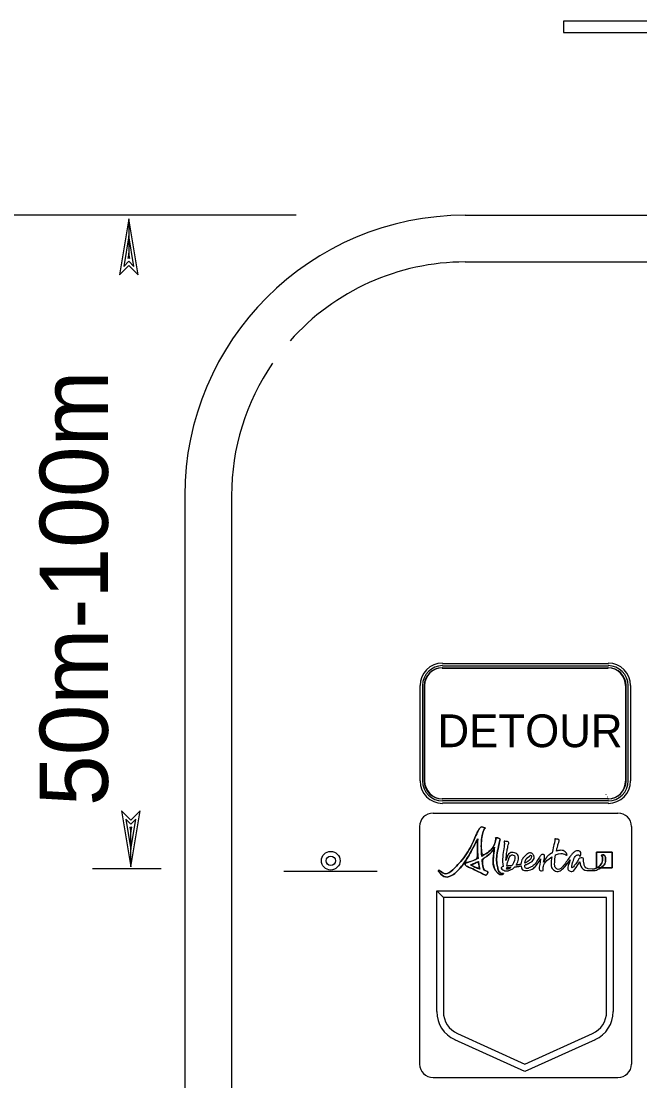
# Model space of a CAD drawing. Extents: x 1806 to 2022, y 110 to 389.
# Drawn here: x 1884.37 to 1900.38, y 193.73 to 221.16 of the extents above; entities that cross this region are included whole.
import ezdxf

# ---------------------------------------------------------------- set-up
doc = ezdxf.new("R2010")
doc.units = 0
for name, color, linetype in [('Level 1', 7, 'Continuous'), ('Level 10', 7, 'Continuous'), ('Level 2', 7, 'Continuous'), ('Level 44', 7, 'Continuous'), ('Level 53', 7, 'Continuous')]:
    doc.layers.add(name, color=color, linetype=linetype)

msp = doc.modelspace()

# ---------------------------------------------------------------- linework, layer by layer
at = {"layer": 'Level 1'}
for points in [[(1887.157, 216.049), (1886.915, 214.597), (1887.157, 214.839), (1887.399, 214.597), (1887.157, 216.049), (1887.157, 215.604), (1887.026, 214.815), (1887.157, 214.946), (1887.288, 214.815), (1887.157, 215.604), (1887.157, 215.154), (1887.133, 215.018), (1887.157, 215.043), (1887.181, 215.018), (1887.157, 215.154), (1887.157, 215.043)], [(1887.207, 199.269), (1887.449, 200.721), (1887.207, 200.479), (1886.965, 200.721), (1887.207, 199.269), (1887.207, 199.714), (1887.338, 200.503), (1887.207, 200.372), (1887.076, 200.503), (1887.207, 199.714), (1887.207, 200.164), (1887.231, 200.3), (1887.207, 200.275), (1887.183, 200.3), (1887.207, 200.164), (1887.207, 200.275)]]:
    msp.add_lwpolyline(points, dxfattribs=at)
at = {"layer": 'Level 10'}
for p, q in [((1891.489, 216.139), (1875.288, 216.139)), ((1895.86, 216.139), (1957.331, 216.139)), ((1895.86, 214.93), (1957.331, 214.93)), ((1888.603, 208.881), (1888.603, 146.057)), ((1889.812, 208.881), (1889.812, 146.057)), ((1887.99, 199.217), (1886.212, 199.217))]:
    msp.add_line(p, q, dxfattribs=at)
for radius, start, end in [(7.258, 90, 180), (6.048, 90, 138.5343), (6.048, 145.494, 180)]:
    msp.add_arc((1895.86, 208.881), radius, start, end, dxfattribs=at)
at = {"layer": 'Level 2'}
for p, q in [((1903.243, 221.163), (1898.405, 221.163)), ((1898.405, 221.163), (1898.405, 220.873)), ((1898.405, 220.873), (1903.243, 220.873)), ((1895.027, 200.661), (1899.812, 200.661)), ((1895.027, 200.661), (1899.812, 200.661)), ((1894.68, 200.314), (1894.68, 194.16)), ((1900.159, 200.314), (1900.159, 194.16)), ((1895.122, 195.522), (1895.122, 198.649)), ((1895.122, 198.649), (1895.293, 198.478)), ((1895.293, 198.478), (1895.122, 198.649)), ((1895.122, 198.649), (1899.688, 198.649)), ((1899.688, 198.649), (1899.688, 195.522)), ((1895.293, 198.478), (1895.293, 195.522)), ((1899.517, 198.478), (1895.293, 198.478)), ((1899.517, 195.522), (1899.517, 198.478)), ((1897.405, 193.969), (1895.59, 194.794)), ((1895.661, 194.95), (1897.405, 194.157)), ((1897.405, 194.157), (1899.149, 194.95)), ((1899.22, 194.794), (1897.405, 193.969)), ((1895.027, 193.813), (1899.812, 193.813))]:
    msp.add_line(p, q, dxfattribs=at)
for centre, radius, start, end in [((1895.027, 200.314), 0.347, 90, 180), ((1899.812, 200.314), 0.347, 0, 90), ((1895.921, 195.522), 0.799, 180, 245.5432), ((1895.921, 195.522), 0.628, 180, 245.5432), ((1898.889, 195.522), 0.628, 294.4568, 0), ((1898.889, 195.522), 0.799, 294.4568, 0), ((1895.027, 194.16), 0.347, 180, 270), ((1899.812, 194.16), 0.347, 270, 0)]:
    msp.add_arc(centre, radius, start, end, dxfattribs=at)
at = {"layer": 'Level 44'}
for p, q in [((1895.261, 204.415), (1899.552, 204.415)), ((1895.271, 204.536), (1899.562, 204.536)), ((1895.271, 204.471), (1899.562, 204.471)), ((1895.271, 204.417), (1899.562, 204.417)), ((1895.271, 204.417), (1899.562, 204.417)), ((1895.271, 204.417), (1899.562, 204.417)), ((1894.696, 201.496), (1894.696, 203.961)), ((1894.761, 201.496), (1894.761, 203.961)), ((1894.805, 201.494), (1894.805, 203.959)), ((1894.815, 201.496), (1894.815, 203.961)), ((1894.815, 201.496), (1894.815, 203.961)), ((1894.815, 201.496), (1894.815, 203.961)), ((1900.004, 203.959), (1900.004, 201.494)), ((1900.014, 203.961), (1900.014, 201.496)), ((1900.014, 203.961), (1900.014, 201.496)), ((1900.014, 203.961), (1900.014, 201.496)), ((1900.068, 203.961), (1900.068, 201.496)), ((1900.133, 203.961), (1900.133, 201.496)), ((1899.505, 201.137), (1899.509, 201.139)), ((1899.552, 201.031), (1895.261, 201.031)), ((1899.562, 201.033), (1895.271, 201.033)), ((1899.562, 201.033), (1895.271, 201.033)), ((1899.562, 201.033), (1895.271, 201.033)), ((1899.562, 200.979), (1895.271, 200.979)), ((1899.562, 200.914), (1895.271, 200.914)), ((1897.627, 201.025), (1897.627, 201.025)), ((1897.637, 201.027), (1897.637, 201.027)), ((1897.637, 201.027), (1897.637, 201.027)), ((1897.637, 201.027), (1897.637, 201.027)), ((1899.534, 201.079), (1899.538, 201.081)), ((1899.558, 201.031), (1899.562, 201.033)), ((1891.165, 199.157), (1893.584, 199.157))]:
    msp.add_line(p, q, dxfattribs=at)
for radius in [0.242, 0.121]:
    msp.add_circle((1892.379, 199.428), radius, dxfattribs=at)
for centre, radius, start, end in [((1895.271, 203.962), 0.581, 90, 180), ((1895.271, 203.962), 0.516, 90, 180), ((1895.261, 203.96), 0.462, 90, 180), ((1895.271, 203.962), 0.462, 90, 180), ((1895.271, 203.962), 0.462, 90, 180), ((1895.271, 203.962), 0.462, 90, 180), ((1899.548, 203.96), 0.462, 0, 90), ((1899.558, 203.962), 0.581, 0, 90), ((1899.558, 203.962), 0.516, 0, 90), ((1899.558, 203.962), 0.462, 0, 90), ((1899.558, 203.962), 0.462, 0, 90), ((1899.558, 203.962), 0.462, 0, 90), ((1895.271, 201.492), 0.581, 180, 270), ((1895.271, 201.492), 0.516, 180, 270), ((1895.261, 201.49), 0.462, 180, 270), ((1895.271, 201.492), 0.462, 180, 270), ((1895.271, 201.492), 0.462, 180, 270), ((1895.271, 201.492), 0.462, 180, 270), ((1899.548, 201.49), 0.462, 270, 0), ((1899.558, 201.492), 0.462, 270, 0), ((1899.558, 201.492), 0.462, 270, 0), ((1899.558, 201.492), 0.581, 270, 0), ((1899.558, 201.492), 0.516, 270, 0), ((1899.558, 201.492), 0.462, 270, 0)]:
    msp.add_arc(centre, radius, start, end, dxfattribs=at)
at = {"layer": 'Level 53'}
msp.add_line((1899.368, 199.244), (1899.267, 199.244), dxfattribs=at)
msp.add_lwpolyline([(1899.368, 199.244), (1899.663, 199.244), (1899.663, 199.652), (1899.256, 199.652), (1899.256, 199.244), (1899.267, 199.244)], dxfattribs=at)
for points, degree in [([(1896.814, 199.096), (1896.77, 199.103), (1896.713, 199.163), (1896.695, 199.261), (1896.664, 199.437), (1896.682, 199.611), (1896.734, 199.871), (1896.744, 199.92), (1896.778, 200.005), (1896.671, 200.021), (1896.637, 200.027), (1896.655, 200.01), (1896.645, 199.965), (1896.604, 199.772), (1896.446, 199.632), (1896.287, 199.539), (1896.271, 199.76), (1896.278, 200.006), (1896.319, 200.157), (1896.354, 200.284), (1896.396, 200.261), (1896.344, 200.287), (1896.29, 200.315), (1896.231, 200.278), (1896.184, 200.184), (1896.136, 200.089), (1895.918, 199.575), (1895.569, 199.227), (1895.39, 199.05), (1895.229, 199.141), (1895.196, 199.169), (1895.17, 199.191), (1895.16, 199.157), (1895.193, 199.121), (1895.337, 198.966), (1895.548, 199.055), (1895.625, 199.132), (1895.837, 199.344), (1896.084, 199.801), (1896.184, 199.995), (1896.175, 199.886), (1896.172, 199.703), (1896.192, 199.488), (1896.084, 199.435), (1895.987, 199.404), (1895.942, 199.392), (1895.892, 199.379), (1895.862, 199.359), (1895.861, 199.336), (1895.86, 199.311), (1895.893, 199.29), (1895.941, 199.267), (1896.026, 199.227), (1896.277, 199.108), (1896.339, 199.072), (1896.392, 199.042), (1896.417, 199.066), (1896.433, 199.099), (1896.454, 199.142), (1896.397, 199.167), (1896.343, 199.183), (1896.322, 199.256), (1896.305, 199.354), (1896.294, 199.461), (1896.422, 199.54), (1896.547, 199.644), (1896.619, 199.775), (1896.601, 199.665), (1896.555, 199.295), (1896.672, 199.138), (1896.697, 199.103), (1896.754, 199.066), (1896.81, 199.071), (1896.836, 199.074), (1896.849, 199.091), (1896.847, 199.096), (1896.844, 199.102), (1896.829, 199.094), (1896.814, 199.096)], 3), ([(1896.287, 199.539), (1896.271, 199.76), (1896.278, 200.006), (1896.319, 200.157), (1896.354, 200.284), (1896.396, 200.261), (1896.344, 200.287), (1896.29, 200.315), (1896.231, 200.278), (1896.184, 200.184), (1896.136, 200.089), (1895.918, 199.575), (1895.569, 199.227), (1895.39, 199.05), (1895.229, 199.141), (1895.196, 199.169), (1895.17, 199.191), (1895.16, 199.157), (1895.193, 199.121), (1895.337, 198.966), (1895.548, 199.055), (1895.625, 199.132), (1895.837, 199.344), (1896.084, 199.801), (1896.184, 199.995)], 3), ([(1896.184, 199.995), (1896.175, 199.886), (1896.172, 199.703), (1896.192, 199.488)], 2), ([(1896.814, 199.096), (1896.77, 199.103), (1896.713, 199.163), (1896.695, 199.261), (1896.664, 199.437), (1896.682, 199.611), (1896.734, 199.871), (1896.744, 199.92), (1896.778, 200.005), (1896.671, 200.021), (1896.637, 200.027), (1896.655, 200.01), (1896.645, 199.965), (1896.604, 199.772), (1896.446, 199.632), (1896.287, 199.539)], 3), ([(1898.218, 199.678), (1898.23, 199.732), (1898.244, 199.787), (1898.259, 199.841), (1898.273, 199.89), (1898.313, 199.975), (1898.208, 199.991), (1898.174, 199.997), (1898.188, 199.98), (1898.177, 199.935), (1898.157, 199.851), (1898.131, 199.743), (1898.113, 199.634)], 3), ([(1896.294, 199.461), (1896.422, 199.54), (1896.547, 199.644), (1896.619, 199.775)], 2), ([(1896.619, 199.775), (1896.601, 199.665), (1896.555, 199.295), (1896.672, 199.138), (1896.697, 199.103), (1896.754, 199.066), (1896.81, 199.071), (1896.836, 199.074), (1896.849, 199.091), (1896.847, 199.096), (1896.844, 199.102), (1896.829, 199.094), (1896.814, 199.096)], 3), ([(1896.912, 199.433), (1896.92, 199.537), (1896.937, 199.663), (1896.96, 199.78), (1896.97, 199.83), (1897.004, 199.915), (1896.897, 199.931), (1896.863, 199.936), (1896.868, 199.92), (1896.871, 199.875), (1896.875, 199.813), (1896.807, 199.441), (1896.842, 199.277)], 3), ([(1896.192, 199.488), (1896.084, 199.435), (1895.987, 199.404), (1895.942, 199.392), (1895.892, 199.379), (1895.862, 199.359), (1895.861, 199.336), (1895.86, 199.311), (1895.893, 199.29), (1895.941, 199.267), (1896.026, 199.227), (1896.277, 199.108), (1896.339, 199.072), (1896.392, 199.042), (1896.417, 199.066), (1896.433, 199.099), (1896.454, 199.142), (1896.397, 199.167), (1896.343, 199.183)], 3), ([(1896.343, 199.183), (1896.322, 199.256), (1896.305, 199.354), (1896.294, 199.461)], 2), ([(1897.174, 199.312), (1897.25, 199.435), (1897.244, 199.601), (1897.133, 199.629), (1897.004, 199.661), (1896.939, 199.537), (1896.912, 199.433)], 3), ([(1896.939, 199.288), (1896.956, 199.419), (1897.025, 199.601), (1897.109, 199.572), (1897.158, 199.555), (1897.132, 199.402), (1897.07, 199.3)], 3), ([(1897.398, 199.316), (1897.416, 199.321), (1897.432, 199.327), (1897.445, 199.333), (1897.606, 199.404), (1897.661, 199.512), (1897.62, 199.578), (1897.582, 199.64), (1897.47, 199.621), (1897.383, 199.529), (1897.339, 199.483), (1897.306, 199.405), (1897.302, 199.334)], 3), ([(1897.303, 199.293), (1897.312, 199.222), (1897.359, 199.167), (1897.468, 199.177), (1897.622, 199.191), (1897.76, 199.381), (1897.811, 199.472)], 3), ([(1897.887, 199.392), (1897.897, 199.442), (1897.913, 199.498), (1897.914, 199.536), (1897.915, 199.576), (1897.888, 199.584), (1897.877, 199.587), (1897.854, 199.594), (1897.826, 199.583), (1897.799, 199.544), (1897.734, 199.453), (1897.653, 199.309), (1897.528, 199.249), (1897.439, 199.206), (1897.4, 199.249), (1897.398, 199.316)], 3), ([(1897.484, 199.521), (1897.539, 199.571), (1897.565, 199.567), (1897.572, 199.554), (1897.588, 199.524), (1897.524, 199.422), (1897.402, 199.365)], 3), ([(1897.402, 199.365), (1897.413, 199.421), (1897.442, 199.481), (1897.484, 199.521)], 2), ([(1897.811, 199.472), (1897.802, 199.374), (1897.738, 199.16), (1897.847, 199.171), (1897.89, 199.175), (1897.871, 199.182), (1897.874, 199.219), (1897.883, 199.348), (1897.991, 199.458), (1898.097, 199.525)], 3), ([(1898.113, 199.634), (1898.026, 199.585), (1897.946, 199.501), (1897.887, 199.392)], 2), ([(1898.097, 199.525), (1898.078, 199.367), (1898.085, 199.225), (1898.157, 199.181), (1898.288, 199.098), (1898.475, 199.315), (1898.578, 199.448)], 3), ([(1899.141, 199.208), (1898.974, 199.208), (1898.931, 199.338), (1898.923, 199.402), (1898.918, 199.445), (1898.927, 199.507), (1898.853, 199.499), (1898.801, 199.493), (1898.755, 199.392), (1898.689, 199.308), (1898.633, 199.235), (1898.608, 199.242), (1898.621, 199.304), (1898.637, 199.382), (1898.702, 199.566), (1898.777, 199.579), (1898.812, 199.586), (1898.824, 199.525), (1898.84, 199.563), (1898.856, 199.601), (1898.841, 199.683), (1898.764, 199.683), (1898.71, 199.683), (1898.645, 199.626), (1898.591, 199.56), (1898.545, 199.503), (1898.31, 199.158), (1898.212, 199.232), (1898.166, 199.267), (1898.17, 199.409), (1898.199, 199.577)], 3), ([(1898.199, 199.577), (1898.315, 199.622), (1898.413, 199.607), (1898.467, 199.58), (1898.495, 199.567), (1898.498, 199.569), (1898.487, 199.599), (1898.47, 199.643), (1898.376, 199.712), (1898.229, 199.68), (1898.225, 199.679), (1898.222, 199.678), (1898.218, 199.678)], 3), ([(1898.578, 199.448), (1898.526, 199.33), (1898.496, 199.179), (1898.575, 199.156), (1898.667, 199.129), (1898.739, 199.282), (1898.824, 199.399)], 3), ([(1899.256, 199.652), (1899.256, 199.652), (1899.256, 199.244), (1899.256, 199.244), (1899.256, 199.244), (1899.267, 199.244), (1899.267, 199.244), (1899.356, 199.297), (1899.415, 199.398), (1899.415, 199.482), (1899.415, 199.553), (1899.377, 199.55), (1899.381, 199.56), (1899.394, 199.589), (1899.484, 199.572), (1899.489, 199.471), (1899.493, 199.385), (1899.448, 199.301), (1899.368, 199.244), (1899.368, 199.244), (1899.663, 199.244), (1899.663, 199.244), (1899.663, 199.244), (1899.663, 199.652), (1899.663, 199.652), (1899.663, 199.652), (1899.256, 199.652), (1899.256, 199.652)], 3), ([(1899.267, 199.244), (1899.356, 199.297), (1899.415, 199.398), (1899.415, 199.482), (1899.415, 199.553), (1899.377, 199.55), (1899.381, 199.56), (1899.394, 199.589), (1899.484, 199.572), (1899.489, 199.471), (1899.493, 199.385), (1899.448, 199.301), (1899.368, 199.244)], 3), ([(1895.997, 199.318), (1896.053, 199.338), (1896.125, 199.368), (1896.201, 199.408)], 2), ([(1895.997, 199.318), (1896.053, 199.338), (1896.125, 199.368), (1896.201, 199.408), (1896.211, 199.322), (1896.222, 199.259), (1896.234, 199.213), (1896.179, 199.233), (1896.1, 199.265), (1895.997, 199.318)], 3), ([(1896.234, 199.213), (1896.179, 199.233), (1896.1, 199.265), (1895.997, 199.318)], 2), ([(1896.201, 199.408), (1896.211, 199.322), (1896.222, 199.259), (1896.234, 199.213)], 2), ([(1896.842, 199.277), (1896.797, 199.262), (1896.778, 199.228), (1896.837, 199.191), (1896.878, 199.166), (1896.967, 199.158), (1897.057, 199.202), (1897.09, 199.218), (1897.118, 199.241), (1897.141, 199.267)], 3), ([(1896.925, 199.209), (1896.931, 199.214), (1896.935, 199.222), (1896.935, 199.231), (1896.935, 199.236), (1896.935, 199.242), (1896.935, 199.248)], 3), ([(1896.962, 199.21), (1896.947, 199.207), (1896.935, 199.208), (1896.925, 199.209)], 2), ([(1896.935, 199.248), (1896.958, 199.249), (1896.994, 199.252), (1897.037, 199.256)], 2), ([(1897.07, 199.3), (1897.029, 199.296), (1896.985, 199.292), (1896.939, 199.288)], 2), ([(1897.037, 199.256), (1897.015, 199.231), (1896.989, 199.214), (1896.962, 199.21)], 2), ([(1897.141, 199.267), (1897.195, 199.274), (1897.252, 199.283), (1897.303, 199.293)], 2), ([(1897.302, 199.334), (1897.265, 199.326), (1897.222, 199.318), (1897.174, 199.312)], 2), ([(1898.824, 199.399), (1898.834, 199.315), (1898.89, 199.17), (1899.116, 199.17), (1899.218, 199.17), (1899.304, 199.199), (1899.368, 199.244)], 3), ([(1899.267, 199.244), (1899.23, 199.222), (1899.187, 199.208), (1899.141, 199.208)], 2)]:
    msp.add_open_spline(points, degree=degree, dxfattribs=at)

# ---------------------------------------------------------------- texts
at = {"layer": 'Level 10'}
msp.add_text('50m-100m', height=1.764, rotation=90, dxfattribs=at).set_placement((1886.614, 200.843))
at = {"layer": 'Level 44'}
msp.add_text('DETOUR', height=0.8479, rotation=360, dxfattribs=at).set_placement((1895.142, 202.367))

doc.saveas('drawing.dxf')
